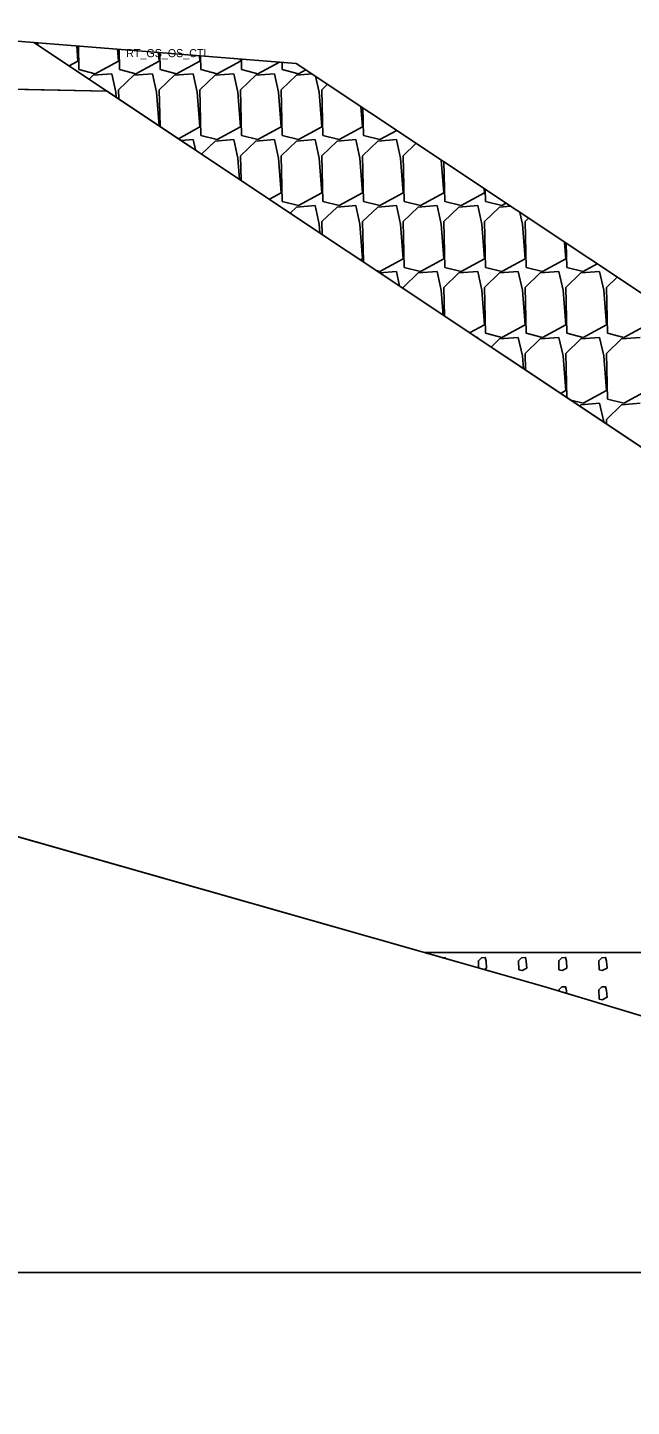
# Model space of a CAD drawing. Extents: x -26 to 2903, y -10 to 63.
# Drawn here: x 165.29 to 174.72, y -2.09 to 19.45 of the extents above; entities that cross this region are included whole.
import ezdxf

# ---------------------------------------------------------------- set-up
doc = ezdxf.new("R2010")
doc.units = 0
for name, color, linetype in [('Default', 7, 'Continuous'), ('Exist Cross Section Cell', 7, 'Continuous'), ('Exist XS Ground Line', 7, 'Continuous'), ('Prop CMT Slope Grass', 7, 'Continuous'), ('Prop CMT Subgrade Earthwork', 7, 'Continuous'), ('Prop XS Earthwork Shape', 7, 'Continuous'), ('Prop XS SE Text', 7, 'Continuous'), ('Scratch_Level_0', 7, 'Continuous')]:
    doc.layers.add(name, color=color, linetype=linetype)

msp = doc.modelspace()

# ---------------------------------------------------------------- linework, layer by layer
at = {"layer": 'Default'}
msp.add_line((165.393, 19.219), (197.354, -2.09), dxfattribs=at)
at = {"layer": 'Exist Cross Section Cell'}
msp.add_line((150, 0), (300, 0), dxfattribs=at)
at = {"layer": 'Exist XS Ground Line'}
for p, q in [((158.457, 8.712), (173.358, 4.469)), ((171.493, 5), (173.358, 4.469)), ((173.358, 4.469), (183.311, 1.47)), ((173.358, 4.469), (174.914, 4))]:
    msp.add_line(p, q, dxfattribs=at)
at = {"layer": 'Prop CMT Slope Grass'}
for p, q in [((162.5, 19.45), (165.392, 19.219)), ((165.392, 19.219), (186.718, 5)), ((171.493, 5), (186.719, 5))]:
    msp.add_line(p, q, dxfattribs=at)
at = {"layer": 'Prop CMT Subgrade Earthwork'}
msp.add_line((166.535, 18.456), (149.987, 18.787), dxfattribs=at)
at = {"layer": 'Prop XS Earthwork Shape'}
msp.add_lwpolyline([(163.445, 18.518), (149.987, 18.787), (136.595, 19.055), (134.335, 19.1), (125.502, 13.212), (126.607, 13.172), (132.699, 12.782), (134.115, 12.628), (135.818, 12.45), (138.979, 12.096), (141.766, 11.887), (144.767, 11.587), (146.165, 11.415), (147.067, 11.271), (148.767, 11.089), (150, 10.856), (151.604, 10.554), (152.413, 10.398), (153.029, 10.26), (156.738, 9.226), (158.457, 8.712), (171.493, 5), (186.718, 5), (166.535, 18.456)], close=True, dxfattribs=at)
at = {"layer": 'Prop XS SE Text'}
for p, q in [((165.392, 19.219), (169.49, 18.891)), ((165.424, 19.198), (165.422, 19.216)), ((165.451, 19.214), (165.452, 19.179)), ((166.08, 18.927), (166.061, 19.165)), ((166.087, 19.163), (166.095, 18.793)), ((166.715, 18.927), (166.7, 19.114)), ((166.723, 19.112), (166.73, 18.793)), ((167.35, 18.927), (167.339, 19.063)), ((167.359, 19.061), (167.365, 18.793)), ((167.985, 18.927), (167.978, 19.012)), ((167.996, 19.01), (168, 18.793)), ((168.62, 18.927), (168.617, 18.961)), ((168.632, 18.96), (168.635, 18.793)), ((165.943, 18.852), (166.08, 18.927)), ((166.095, 18.793), (166.351, 18.729)), ((166.351, 18.729), (166.715, 18.927)), ((166.73, 18.793), (166.986, 18.729)), ((166.986, 18.729), (167.35, 18.927)), ((167.365, 18.793), (167.621, 18.729)), ((167.621, 18.729), (167.985, 18.927)), ((168, 18.793), (168.256, 18.729)), ((168.256, 18.729), (168.62, 18.927)), ((168.635, 18.793), (168.891, 18.729)), ((168.891, 18.729), (169.228, 18.912)), ((169.268, 18.909), (169.27, 18.793)), ((169.27, 18.793), (169.526, 18.729)), ((169.49, 18.891), (195.712, 1.41)), ((169.526, 18.729), (169.64, 18.791)), ((166.316, 18.706), (166.253, 18.645)), ((166.609, 18.729), (166.316, 18.706)), ((166.672, 18.439), (166.609, 18.729)), ((166.951, 18.706), (166.715, 18.477)), ((167.244, 18.729), (166.951, 18.706)), ((167.307, 18.439), (167.244, 18.729)), ((167.586, 18.706), (167.35, 18.477)), ((167.879, 18.729), (167.586, 18.706)), ((167.942, 18.439), (167.879, 18.729)), ((168.221, 18.706), (167.985, 18.477)), ((168.514, 18.729), (168.221, 18.706)), ((168.577, 18.439), (168.514, 18.729)), ((168.856, 18.706), (168.62, 18.477)), ((169.149, 18.729), (168.856, 18.706)), ((169.212, 18.439), (169.149, 18.729)), ((169.491, 18.706), (169.255, 18.477)), ((169.738, 18.725), (169.491, 18.706)), ((169.847, 18.439), (169.792, 18.689)), ((169.98, 18.564), (169.89, 18.477)), ((166.678, 18.362), (166.672, 18.439)), ((166.715, 18.477), (166.718, 18.335)), ((167.348, 17.915), (167.307, 18.439)), ((167.35, 18.477), (167.362, 17.906)), ((167.985, 17.897), (167.942, 18.439)), ((167.985, 18.477), (168, 17.764)), ((168.62, 17.897), (168.577, 18.439)), ((168.62, 18.477), (168.635, 17.764)), ((169.255, 17.897), (169.212, 18.439)), ((169.255, 18.477), (169.27, 17.764)), ((169.89, 17.897), (169.847, 18.439)), ((169.89, 18.477), (169.905, 17.764)), ((170.525, 17.897), (170.499, 18.218)), ((170.531, 18.197), (170.54, 17.764)), ((167.649, 17.714), (167.985, 17.897)), ((168.256, 17.699), (168.62, 17.897)), ((168.891, 17.699), (169.255, 17.897)), ((169.526, 17.699), (169.89, 17.897)), ((170.161, 17.699), (170.525, 17.897)), ((167.879, 17.699), (167.694, 17.685)), ((167.914, 17.538), (167.879, 17.699)), ((168, 17.764), (168.256, 17.699)), ((168.221, 17.676), (168.011, 17.473)), ((168.514, 17.699), (168.221, 17.676)), ((168.577, 17.409), (168.514, 17.699)), ((168.856, 17.676), (168.62, 17.447)), ((168.635, 17.764), (168.891, 17.699)), ((169.149, 17.699), (168.856, 17.676)), ((169.212, 17.409), (169.149, 17.699)), ((169.491, 17.676), (169.255, 17.447)), ((169.27, 17.764), (169.526, 17.699)), ((169.783, 17.699), (169.491, 17.676)), ((169.847, 17.409), (169.783, 17.699)), ((170.126, 17.676), (169.89, 17.447)), ((169.905, 17.764), (170.161, 17.699)), ((170.418, 17.699), (170.126, 17.676)), ((170.482, 17.409), (170.418, 17.699)), ((170.761, 17.676), (170.525, 17.447)), ((170.54, 17.764), (170.796, 17.699)), ((171.053, 17.699), (170.761, 17.676)), ((170.796, 17.699), (171.061, 17.843)), ((171.117, 17.409), (171.053, 17.699)), ((171.175, 17.768), (171.175, 17.764)), ((171.175, 17.764), (171.184, 17.761)), ((171.361, 17.643), (171.16, 17.447)), ((168.603, 17.078), (168.577, 17.409)), ((168.62, 17.447), (168.628, 17.062)), ((169.255, 16.867), (169.212, 17.409)), ((169.255, 17.447), (169.27, 16.734)), ((169.89, 16.867), (169.847, 17.409)), ((169.89, 17.447), (169.905, 16.734)), ((170.525, 16.867), (170.482, 17.409)), ((170.525, 17.447), (170.54, 16.734)), ((171.16, 16.867), (171.117, 17.409)), ((171.16, 17.447), (171.175, 16.734)), ((171.794, 16.867), (171.754, 17.381)), ((171.796, 17.353), (171.81, 16.734)), ((169.07, 16.767), (169.255, 16.867)), ((169.526, 16.669), (169.89, 16.867)), ((170.161, 16.669), (170.525, 16.867)), ((170.796, 16.669), (171.16, 16.867)), ((171.431, 16.669), (171.794, 16.867)), ((172.066, 16.669), (172.429, 16.867)), ((172.429, 16.867), (172.424, 16.935)), ((172.441, 16.924), (172.445, 16.734)), ((169.27, 16.734), (169.526, 16.669)), ((169.491, 16.646), (169.393, 16.552)), ((169.783, 16.669), (169.491, 16.646)), ((169.847, 16.38), (169.783, 16.669)), ((170.126, 16.646), (169.89, 16.418)), ((169.905, 16.734), (170.161, 16.669)), ((170.418, 16.669), (170.126, 16.646)), ((170.482, 16.38), (170.418, 16.669)), ((170.761, 16.646), (170.525, 16.418)), ((170.54, 16.734), (170.796, 16.669)), ((171.053, 16.669), (170.761, 16.646)), ((171.117, 16.38), (171.053, 16.669)), ((171.395, 16.646), (171.16, 16.418)), ((171.175, 16.734), (171.431, 16.669)), ((171.688, 16.669), (171.395, 16.646)), ((171.752, 16.38), (171.688, 16.669)), ((172.03, 16.646), (171.794, 16.418)), ((171.81, 16.734), (172.066, 16.669)), ((172.323, 16.669), (172.03, 16.646)), ((172.387, 16.38), (172.323, 16.669)), ((172.665, 16.646), (172.429, 16.418)), ((172.445, 16.734), (172.701, 16.669)), ((172.836, 16.66), (172.665, 16.646)), ((172.701, 16.669), (172.767, 16.706)), ((169.858, 16.242), (169.847, 16.38)), ((169.89, 16.418), (169.894, 16.218)), ((170.525, 15.838), (170.482, 16.38)), ((170.525, 16.418), (170.538, 15.788)), ((171.16, 15.838), (171.117, 16.38)), ((171.16, 16.418), (171.175, 15.704)), ((171.794, 15.838), (171.752, 16.38)), ((171.794, 16.418), (171.81, 15.704)), ((172.429, 15.838), (172.387, 16.38)), ((172.429, 16.418), (172.445, 15.704)), ((173.022, 16.38), (172.982, 16.563)), ((173.064, 15.838), (173.022, 16.38)), ((173.119, 16.471), (173.064, 16.418)), ((173.064, 16.418), (173.08, 15.704)), ((173.699, 15.838), (173.679, 16.098)), ((173.707, 16.08), (173.715, 15.704)), ((170.491, 15.82), (170.525, 15.838)), ((170.796, 15.64), (171.16, 15.838)), ((171.431, 15.64), (171.794, 15.838)), ((172.066, 15.64), (172.429, 15.838)), ((172.701, 15.64), (173.064, 15.838)), ((173.336, 15.64), (173.699, 15.838)), ((173.97, 15.64), (174.188, 15.758)), ((170.739, 15.654), (170.796, 15.64)), ((171.053, 15.64), (170.792, 15.619)), ((171.103, 15.411), (171.053, 15.64)), ((171.395, 15.617), (171.16, 15.388)), ((171.175, 15.704), (171.431, 15.64)), ((171.688, 15.64), (171.395, 15.617)), ((171.752, 15.35), (171.688, 15.64)), ((172.03, 15.617), (171.794, 15.388)), ((171.81, 15.704), (172.066, 15.64)), ((172.323, 15.64), (172.03, 15.617)), ((172.387, 15.35), (172.323, 15.64)), ((172.665, 15.617), (172.429, 15.388)), ((172.445, 15.704), (172.701, 15.64)), ((172.958, 15.64), (172.665, 15.617)), ((173.022, 15.35), (172.958, 15.64)), ((173.3, 15.617), (173.064, 15.388)), ((173.08, 15.704), (173.336, 15.64)), ((173.593, 15.64), (173.3, 15.617)), ((173.657, 15.35), (173.593, 15.64)), ((173.935, 15.617), (173.699, 15.388)), ((173.715, 15.704), (173.97, 15.64)), ((174.228, 15.64), (173.935, 15.617)), ((174.292, 15.35), (174.228, 15.64)), ((174.501, 15.55), (174.334, 15.388)), ((171.16, 15.388), (171.16, 15.374)), ((171.783, 14.959), (171.752, 15.35)), ((171.794, 15.388), (171.804, 14.944)), ((172.429, 14.808), (172.387, 15.35)), ((172.429, 15.388), (172.445, 14.675)), ((173.064, 14.808), (173.022, 15.35)), ((173.064, 15.388), (173.08, 14.675)), ((173.699, 14.808), (173.657, 15.35)), ((173.699, 15.388), (173.715, 14.675)), ((174.334, 14.808), (174.292, 15.35)), ((174.334, 15.388), (174.35, 14.675)), ((172.197, 14.682), (172.429, 14.808)), ((172.445, 14.675), (172.701, 14.61)), ((172.701, 14.61), (173.064, 14.808)), ((173.08, 14.675), (173.336, 14.61)), ((173.336, 14.61), (173.699, 14.808)), ((173.715, 14.675), (173.97, 14.61)), ((173.97, 14.61), (174.334, 14.808)), ((174.35, 14.675), (174.605, 14.61)), ((174.605, 14.61), (174.969, 14.808)), ((172.323, 14.61), (172.307, 14.609)), ((172.326, 14.596), (172.323, 14.61)), ((172.665, 14.587), (172.532, 14.459)), ((172.958, 14.61), (172.665, 14.587)), ((173.022, 14.321), (172.958, 14.61)), ((173.3, 14.587), (173.064, 14.359)), ((173.593, 14.61), (173.3, 14.587)), ((173.657, 14.321), (173.593, 14.61)), ((173.935, 14.587), (173.699, 14.359)), ((174.228, 14.61), (173.935, 14.587)), ((174.292, 14.321), (174.228, 14.61)), ((174.57, 14.587), (174.334, 14.359)), ((174.863, 14.61), (174.57, 14.587)), ((173.037, 14.122), (173.022, 14.321)), ((173.064, 14.359), (173.07, 14.1)), ((173.699, 13.779), (173.657, 14.321)), ((173.699, 14.359), (173.714, 13.671)), ((174.334, 13.779), (174.292, 14.321)), ((174.334, 14.359), (174.35, 13.645)), ((173.618, 13.735), (173.699, 13.779)), ((173.776, 13.63), (173.97, 13.581)), ((174.228, 13.581), (173.935, 13.558)), ((173.97, 13.581), (174.334, 13.779)), ((174.292, 13.291), (174.228, 13.581)), ((174.35, 13.645), (174.605, 13.581)), ((174.863, 13.581), (174.57, 13.558)), ((174.605, 13.581), (174.969, 13.779)), ((173.935, 13.558), (173.914, 13.537)), ((174.57, 13.558), (174.334, 13.329)), ((174.292, 13.285), (174.292, 13.291)), ((174.334, 13.329), (174.336, 13.256))]:
    msp.add_line(p, q, dxfattribs=at)
for points in [[(171.817, 4.907), (171.814, 4.923), (171.773, 4.92)], [(172.422, 4.735), (172.462, 4.757), (172.454, 4.865), (172.441, 4.923), (172.382, 4.919), (172.335, 4.873), (172.338, 4.759)], [(173.711, 4.362), (173.708, 4.409), (173.695, 4.467), (173.636, 4.463), (173.589, 4.417), (173.59, 4.399)]]:
    msp.add_lwpolyline(points, dxfattribs=at)
for points in [[(172.965, 4.73), (173.016, 4.717), (173.089, 4.757), (173.081, 4.865), (173.068, 4.923), (173.009, 4.919), (172.962, 4.873)], [(173.592, 4.73), (173.643, 4.717), (173.716, 4.757), (173.708, 4.865), (173.695, 4.923), (173.636, 4.919), (173.589, 4.873)], [(174.219, 4.73), (174.27, 4.717), (174.343, 4.757), (174.335, 4.865), (174.322, 4.923), (174.263, 4.919), (174.216, 4.873)], [(174.219, 4.274), (174.27, 4.261), (174.343, 4.301), (174.335, 4.409), (174.322, 4.467), (174.263, 4.463), (174.216, 4.417)]]:
    msp.add_lwpolyline(points, close=True, dxfattribs=at)

# ---------------------------------------------------------------- texts
at = {"layer": 'Scratch_Level_0'}
msp.add_text('RT_GS_OS_CTL', height=0.125, dxfattribs=at).set_placement((166.833, 18.988))
msp.add_text('RT_GS_OS_CTL', height=0.125, dxfattribs=at).set_placement((166.833, 18.988))

doc.saveas('drawing.dxf')
